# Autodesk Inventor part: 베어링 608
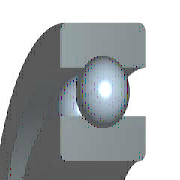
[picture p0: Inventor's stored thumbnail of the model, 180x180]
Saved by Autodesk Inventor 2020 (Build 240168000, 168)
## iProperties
Created: 2012-02
Part Number: 베어링 608
Material: 강철, 연강
Description: 깊은 그루브 볼 베어링
Document SubType Name: Modeling
Standard: KS B 2023
Designer: mduedu
Standards Organization: KS
Language: ko-KR
Size Designation: 608 - 8 x 22 x 7
Categories: <MemberInstance><Categories><Category DisplayName="샤프트 부품" InternalName="7f7aeb1f-a693-4053-b835-cee3144e0d98" Mnemonic="SHFT"><Category DisplayName="베어링" Inter
Density: 1 g/cm^3
Appearance: 보라색
IsCustomPart: 1
Author: mduedu
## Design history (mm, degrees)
sketch "스케치" dims "d0" = 3.64 (= -0.26 x WD + 0.26 x BD)
  geometry: L1 (1.68, 7.5)-(5.32, 7.5); L2 (3.5, 7.5)-(3.5, 5.68); L3 (3.5, 7.5)-(3.5, 9.32); L4 (2.148, 6.282)-(0, 6.282); L5 (0, 4)-(7, 4); L6 (2.148, 8.718)-(0, 8.718); L7 (0, 11)-(7, 11); L8 (7, 4)-(7, 6.282); L9 (4.852, 6.282)-(7, 6.282); L10 (4.852, 8.718)-(7, 8.718); L11 (7, 11)-(7, 8.718); L12 (-1.4, 0)-(8.4, 0) reference; L13 (0, -0.3)-(0, 5.3) reference
  constraints: 22 end point, 4 point on line, 2 collinear, 2 perpendicular, 2 symmetric about line, 1 midpoint, 1 parallel, 14 other
  dimensions: "d9" = 8 diameter of L5 L12 (= WD); "d11" = 22 diameter of L7 L12 (= BD); "d12" = 7 distance between parallel lines of L8 L13 (= KB); "d13" = 12.564 diameter of L9 L12 (= 0.326 x BD + 0.674 x WD)
revolve "본체" stored, may be unused: angle "d6" = 90 deg
revolve "볼" stored, may be unused: angle "d7" = 90 deg
pattern_circular "IDS_ARRAYBALL[SIMPL:T]" dims angle "d3" = 360 deg
body "Solid1"
fillet "모깎기1" dims "d1" = 0.3 (= KRS)
other parameters: "WD" = 8 [user parameter; used in 5 equation terms], "BD" = 22 [user parameter; used in 5 equation terms], "KB" = 7 [user parameter; used in 1 equation term], "KRS" = 0.3 [user parameter; used in 1 equation term], "d4" = 0, "d5" = 0, "d8" = 0, "d14" = 0, "d15" = 0, "BBA" = 0 [user parameter], "BC0" = 1370000 [user parameter], "BC" = 3250000 [user parameter], "BR" = 11 (= 0.5 x BD) [user parameter], "WR" = 4 (= 0.5 x WD) [user parameter]
